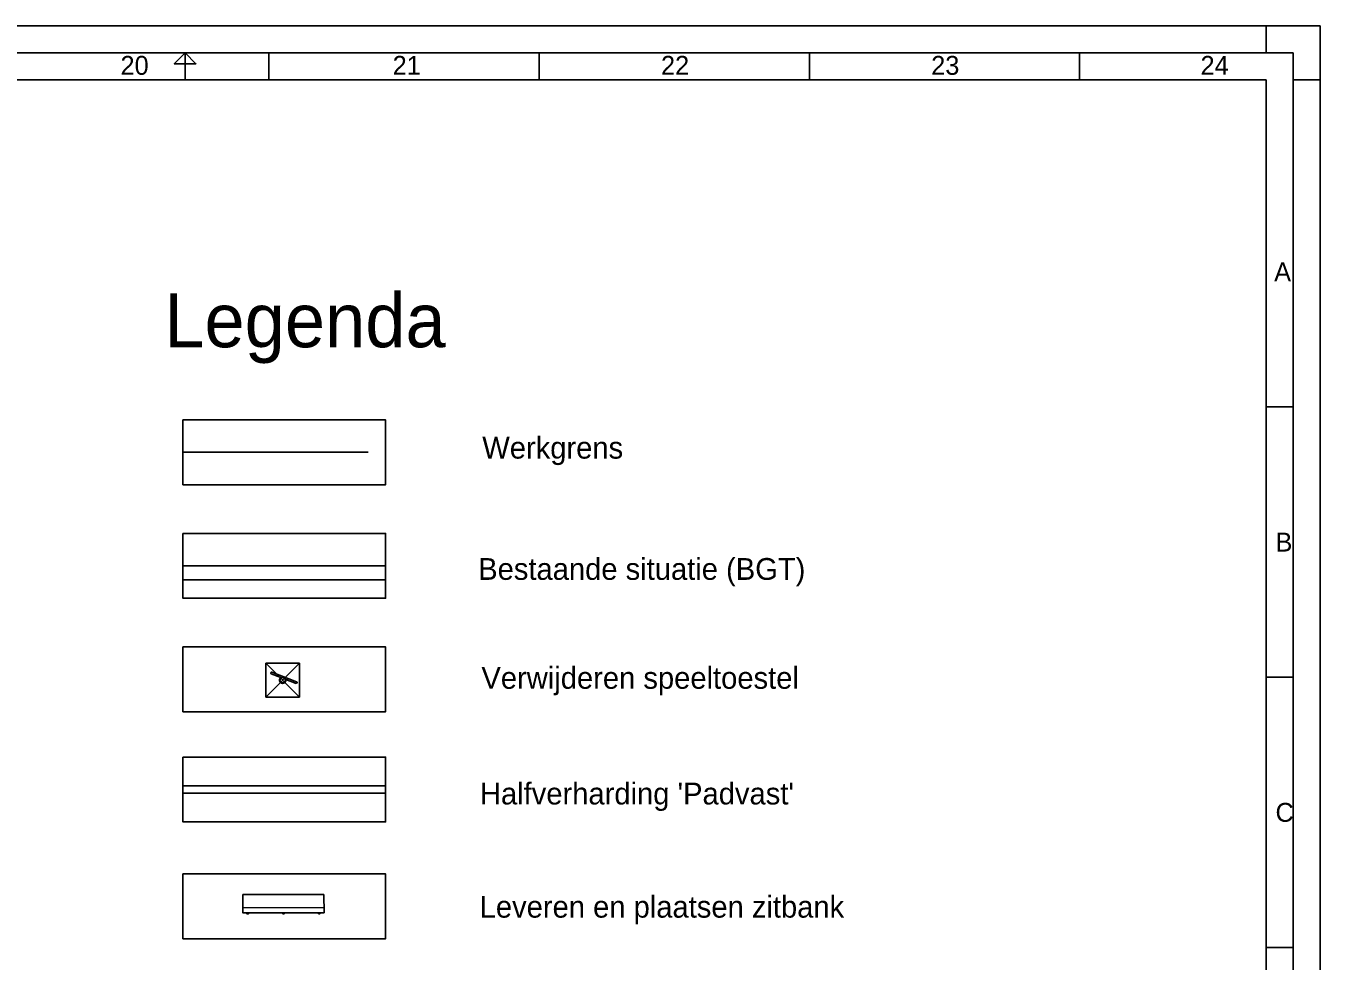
# Model space of a CAD drawing. Extents: x 192672 to 192910, y 446344 to 446512.
# Drawn here: x 192861.65 to 192909.54, y 446477.15 to 446511.76 of the extents above; entities that cross this region are included whole.
import ezdxf

# ---------------------------------------------------------------- set-up
doc = ezdxf.new("R2010")
doc.units = 0
for name, color, linetype in [('( Toegevoegd 29-11-2021 14_41_42) wegdeel vlak', 7, 'Continuous'), ('201011 legenda', 7, 'Continuous'), ('B-GV-KG-GRENS_WERKGRENS-G', 7, 'Continuous'), ('N-GV-IE-MEUBILAIR_WEGMEUBILAIR_ZITBANK-S', 7, 'Continuous'), ('N-GV-VH-VERHARDING_HALFVERHARDING-G', 7, 'Continuous'), ('pand op maaiveld vlak', 7, 'Continuous'), ('speelvoorziening', 7, 'Continuous'), ('V-GV-IE-MEUBILAIR_WEGMEUBILAIR_SPEELTOESTEL-G', 7, 'Continuous'), ('X-XX-AL-TEKENBLAD-S', 7, 'Continuous')]:
    doc.layers.add(name, color=color, linetype=linetype)

msp = doc.modelspace()

# ---------------------------------------------------------------- linework, layer by layer
at = {"layer": '( Toegevoegd 29-11-2021 14_41_42) wegdeel vlak'}
msp.add_line((192867.462, 446491.779), (192874.962, 446491.779), dxfattribs=at)
at = {"layer": '201011 legenda'}
for points in [[(192867.462, 446497.179), (192874.962, 446497.179), (192874.962, 446494.779), (192867.462, 446494.779)], [(192867.462, 446492.979), (192874.962, 446492.979), (192874.962, 446490.579), (192867.462, 446490.579)], [(192867.462, 446488.779), (192874.962, 446488.779), (192874.962, 446486.379), (192867.462, 446486.379)], [(192867.462, 446484.702), (192874.962, 446484.702), (192874.962, 446482.302), (192867.462, 446482.302)], [(192867.462, 446480.379), (192874.962, 446480.379), (192874.962, 446477.979), (192867.462, 446477.979)]]:
    msp.add_lwpolyline(points, close=True, dxfattribs=at)
at = {"layer": 'B-GV-KG-GRENS_WERKGRENS-G'}
msp.add_line((192874.314, 446495.979), (192867.462, 446495.979), dxfattribs=at)
at = {"layer": 'N-GV-IE-MEUBILAIR_WEGMEUBILAIR_ZITBANK-S'}
msp.add_line((192872.684, 446479.131), (192869.684, 446479.126), dxfattribs=at)
msp.add_lwpolyline([(192872.683, 446479.621), (192872.685, 446478.942), (192869.685, 446478.936), (192869.683, 446479.616)], close=True, dxfattribs=at)
for points in [[(192869.885, 446478.937), (192869.885, 446478.902), (192869.834, 446478.901), (192869.834, 446478.937)], [(192871.21, 446478.939), (192871.21, 446478.904), (192871.159, 446478.904), (192871.159, 446478.939)], [(192872.535, 446478.941), (192872.535, 446478.906), (192872.485, 446478.906), (192872.485, 446478.941)]]:
    msp.add_lwpolyline(points, dxfattribs=at)
at = {"layer": 'N-GV-VH-VERHARDING_HALFVERHARDING-G'}
msp.add_lwpolyline([(192867.462, 446483.637), (192874.962, 446483.637), (192874.962, 446483.366), (192867.462, 446483.366)], close=True, dxfattribs=at)
at = {"layer": 'pand op maaiveld vlak'}
msp.add_line((192867.462, 446491.257), (192874.962, 446491.257), dxfattribs=at)
at = {"layer": 'speelvoorziening'}
for p, q in [((192870.727, 446487.787), (192871.089, 446487.647)), ((192871.67, 446487.485), (192870.748, 446487.842)), ((192871.269, 446487.577), (192871.648, 446487.43))]:
    msp.add_line(p, q, dxfattribs=at)
msp.add_circle((192871.154, 446487.547), 0.1, dxfattribs=at)
for centre, radius, start, end in [((192870.737, 446487.814), 0.0297, 68.8387, 248.8387), ((192871.154, 446487.547), 0.119, 123.05, 14.6275), ((192871.154, 446487.547), 0.1, 0, 180), ((192871.154, 446487.547), 0.1, 180, 0), ((192871.659, 446487.458), 0.0297, 248.8387, 68.8387)]:
    msp.add_arc(centre, radius, start, end, dxfattribs=at)
at = {"layer": 'V-GV-IE-MEUBILAIR_WEGMEUBILAIR_SPEELTOESTEL-G'}
for p, q in [((192870.529, 446488.172), (192870.529, 446486.922)), ((192870.529, 446488.172), (192871.779, 446488.172)), ((192870.529, 446488.172), (192871.779, 446486.922)), ((192870.529, 446486.922), (192871.779, 446488.172)), ((192871.779, 446488.172), (192871.779, 446486.922)), ((192870.529, 446486.922), (192871.779, 446486.922))]:
    msp.add_line(p, q, dxfattribs=at)
at = {"layer": 'X-XX-AL-TEKENBLAD-S'}
for p, q in [((192909.543, 446511.756), (192671.743, 446511.756)), ((192909.543, 446343.556), (192909.543, 446511.756)), ((192908.543, 446510.756), (192674.743, 446510.756)), ((192867.543, 446509.756), (192867.543, 446510.756)), ((192870.643, 446510.756), (192870.643, 446509.756)), ((192880.643, 446510.756), (192880.643, 446509.756)), ((192890.643, 446510.756), (192890.643, 446509.756)), ((192900.643, 446510.756), (192900.643, 446509.756)), ((192908.543, 446344.556), (192908.543, 446510.756)), ((192908.543, 446497.656), (192907.543, 446497.656)), ((192908.543, 446487.656), (192907.543, 446487.656)), ((192908.543, 446477.656), (192907.543, 446477.656))]:
    msp.add_line(p, q, dxfattribs=at)
for points in [[(192909.543, 446509.756), (192909.543, 446511.756), (192907.543, 446511.756), (192907.543, 446510.756), (192908.543, 446510.756), (192908.543, 446509.756), (192909.543, 446509.756)], [(192867.543, 446510.356), (192867.543, 446510.756), (192867.143, 446510.356), (192867.543, 446510.356)], [(192867.543, 446510.756), (192867.543, 446510.356), (192867.943, 446510.356), (192867.543, 446510.756)]]:
    msp.add_lwpolyline(points, dxfattribs=at)
msp.add_lwpolyline([(192675.743, 446345.556), (192907.543, 446345.556), (192907.543, 446509.756), (192675.743, 446509.756)], close=True, dxfattribs=at)

# ---------------------------------------------------------------- texts
at = {"layer": '201011 legenda'}
for s, height, p in [('Legenda', 2, (192866.773, 446499.865)), ('Werkgrens', 0.8064, (192878.54, 446495.745)), ('Bestaande situatie (BGT)', 0.8064, (192878.389, 446491.259)), ('Verwijderen speeltoestel', 0.8064, (192878.508, 446487.23)), ("Halfverharding 'Padvast'", 0.8064, (192878.453, 446482.949)), ('Leveren en plaatsen zitbank', 0.8064, (192878.444, 446478.761))]:
    msp.add_text(s, height=height, dxfattribs=at).set_placement(p)
at = {"layer": 'X-XX-AL-TEKENBLAD-S'}
for s, p in [('20', (192865.154, 446509.945)), ('21', (192875.224, 446509.945)), ('22', (192885.154, 446509.945)), ('23', (192895.153, 446509.945)), ('24', (192905.119, 446509.945)), ('A', (192907.843, 446502.306)), ('B', (192907.893, 446492.306)), ('C', (192907.893, 446482.306))]:
    msp.add_text(s, height=0.7, dxfattribs=at).set_placement(p)

doc.saveas('drawing.dxf')
